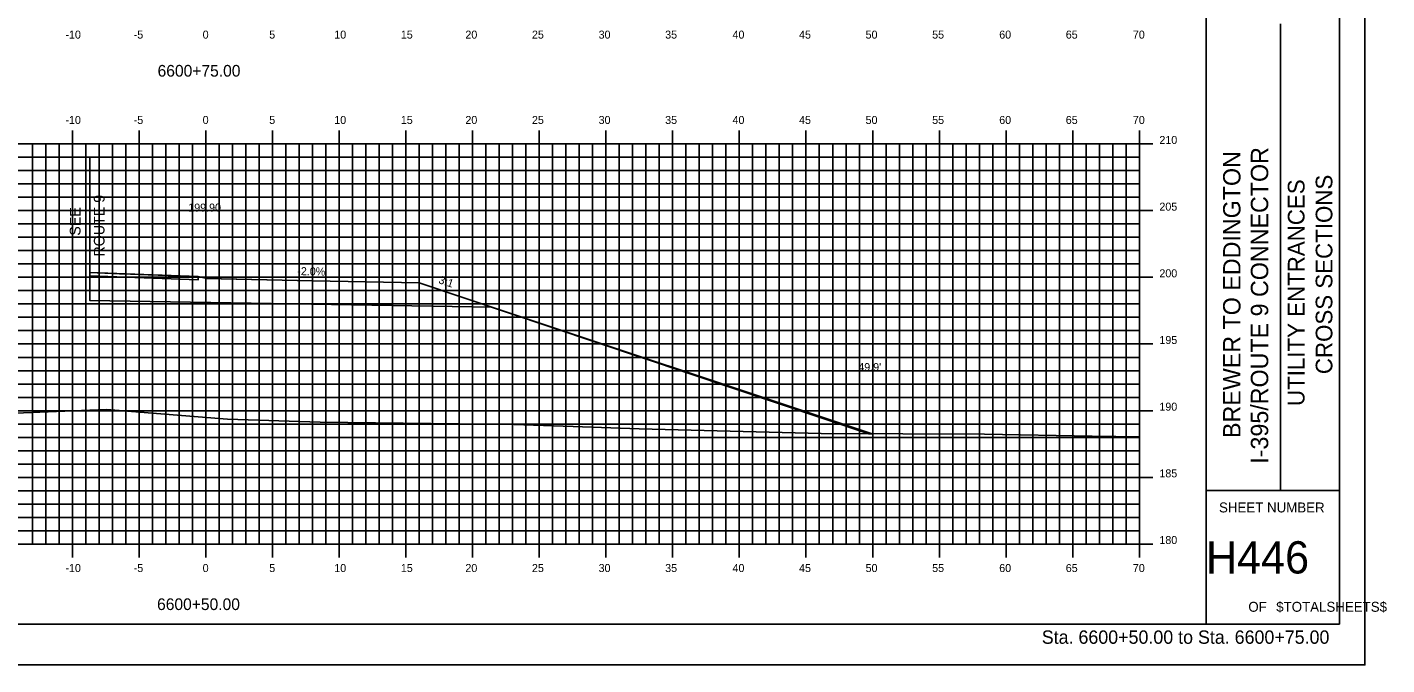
# Model space of a CAD drawing. Extents: x 1723296 to 1723468, y 459560 to 459670.
# Drawn here: x 1723365.8 to 1723467.8, y 459559.6 to 459607.4 of the extents above; entities that cross this region are included whole.
import ezdxf

# ---------------------------------------------------------------- set-up
doc = ezdxf.new("R2010")
doc.units = 0
for name, color, linetype in [('ANNOTATION', 7, 'Continuous'), ('BORDER', 7, 'Continuous'), ('D_Roadway_Centerline', 7, 'Continuous'), ('D_Roadway_Centerline_Text', 7, 'Continuous'), ('D_Roadway_Drive_Gravel', 7, 'Continuous'), ('D_Roadway_Edge_Shoulder', 7, 'Continuous'), ('D_Roadway_Edge_TW', 7, 'Continuous'), ('D_Roadway_Pavement', 7, 'Continuous'), ('D_Roadway_SlopeLines', 7, 'Continuous'), ('D_Roadway_SubGrade', 7, 'Continuous'), ('D_Text_Standard', 7, 'Continuous'), ('H_V ANNOTATION', 7, 'Continuous'), ('HIGHWAY_TITLE', 7, 'Continuous'), ('MAJOR', 7, 'Continuous'), ('MINOR', 7, 'Continuous'), ('PLOT BOUNDARY', 7, 'Continuous'), ('S_Roadway_Centerline', 7, 'Continuous')]:
    doc.layers.add(name, color=color, linetype=linetype)

msp = doc.modelspace()

# ---------------------------------------------------------------- linework, layer by layer
msp.add_lwpolyline([(1723379.2, 459588.51), (1723387.2, 459588.35), (1723395.2, 459588.19), (1723398.39, 459587.13), (1723428.91, 459576.88), (1723428.99, 459576.88), (1723429.03, 459576.88), (1723429.15, 459576.88)])
at = {"layer": 'BORDER'}
for p, q in [((1723454.2, 459562.61), (1723454.2, 459667.61)), ((1723459.79, 459572.62), (1723459.79, 459607.62)), ((1723454.2, 459572.62), (1723464.2, 459572.62))]:
    msp.add_line(p, q, dxfattribs=at)
msp.add_lwpolyline([(1723304.2, 459562.61), (1723464.2, 459562.61), (1723464.2, 459667.61), (1723304.2, 459667.61)], close=True, dxfattribs=at)
at = {"layer": 'D_Roadway_Centerline'}
msp.add_lwpolyline([(1723370.5, 459588.96), (1723372.73, 459588.88), (1723373.54, 459588.85), (1723374.88, 459588.8), (1723378.62, 459588.66), (1723379.24, 459588.51)], dxfattribs=at)
at = {"layer": 'D_Roadway_Drive_Gravel'}
msp.add_lwpolyline([(1723379.24, 459588.51), (1723387.2, 459588.35), (1723395.2, 459588.19), (1723398.39, 459587.13)], dxfattribs=at)
at = {"layer": 'D_Roadway_Edge_Shoulder'}
msp.add_lwpolyline([(1723370.5, 459588.96), (1723378.62, 459588.66), (1723378.62, 459588.41), (1723370.5, 459588.71)], close=True, dxfattribs=at)
msp.add_lwpolyline([(1723370.5, 459588.96), (1723378.62, 459588.66), (1723378.62, 459588.41), (1723370.5, 459588.71)], close=True, dxfattribs=at)
at = {"layer": 'D_Roadway_Edge_TW'}
msp.add_line((1723370.5, 459588.96), (1723370.5, 459588.71), dxfattribs=at)
msp.add_line((1723370.5, 459588.96), (1723370.5, 459588.71), dxfattribs=at)
msp.add_line((1723370.5, 459588.96), (1723370.5, 459588.71), dxfattribs=at)
at = {"layer": 'D_Roadway_Pavement'}
msp.add_line((1723370.5, 459588.71), (1723370.5, 459588.29), dxfattribs=at)
msp.add_line((1723370.5, 459588.71), (1723370.5, 459588.29), dxfattribs=at)
msp.add_lwpolyline([(1723370.5, 459588.71), (1723370.5, 459588.29)], dxfattribs=at)
at = {"layer": 'D_Roadway_SlopeLines'}
for points in [[(1723378.62, 459588.66), (1723379.24, 459588.51)], [(1723378.62, 459588.66), (1723379.24, 459588.51)], [(1723378.62, 459588.66), (1723379.24, 459588.51)], [(1723378.62, 459588.66), (1723379.24, 459588.51)], [(1723378.62, 459588.66), (1723379.24, 459588.51)], [(1723378.62, 459588.66), (1723379.24, 459588.51)], [(1723378.62, 459588.66), (1723379.24, 459588.51)], [(1723395.2, 459588.19), (1723398.39, 459587.13), (1723429.15, 459576.88)]]:
    msp.add_lwpolyline(points, dxfattribs=at)
at = {"layer": 'D_Roadway_SubGrade'}
for p, q in [((1723370.5, 459597.66), (1723370.5, 459586.87)), ((1723370.5, 459588.71), (1723370.5, 459586.87)), ((1723387.11, 459586.6), (1723400.66, 459586.37))]:
    msp.add_line(p, q, dxfattribs=at)
for points in [[(1723387.11, 459586.6), (1723370.5, 459586.87), (1723370.5, 459588.29), (1723370.5, 459588.71), (1723378.62, 459588.41), (1723378.62, 459588.66), (1723379.24, 459588.51)], [(1723387.11, 459586.6), (1723370.5, 459586.87), (1723370.5, 459588.71), (1723378.62, 459588.41), (1723378.62, 459588.66), (1723379.24, 459588.51)], [(1723370.5, 459588.71), (1723378.62, 459588.41), (1723378.62, 459588.66), (1723379.24, 459588.51)], [(1723370.5, 459588.71), (1723378.62, 459588.41), (1723378.62, 459588.66), (1723379.24, 459588.51)], [(1723370.5, 459588.29), (1723370.5, 459588.71), (1723370.5, 459586.87)], [(1723387.11, 459586.6), (1723370.5, 459586.87)], [(1723387.11, 459586.6), (1723370.5, 459586.87)]]:
    msp.add_lwpolyline(points, dxfattribs=at)
at = {"layer": 'MAJOR'}
for p, q in [((1723369.2, 459599.61), (1723369.2, 459598.61)), ((1723374.2, 459599.61), (1723374.2, 459598.61)), ((1723379.2, 459599.61), (1723379.2, 459598.61)), ((1723384.2, 459599.61), (1723384.2, 459598.61)), ((1723389.2, 459599.61), (1723389.2, 459598.61)), ((1723394.2, 459599.61), (1723394.2, 459598.61)), ((1723399.2, 459599.61), (1723399.2, 459598.61)), ((1723404.2, 459599.61), (1723404.2, 459598.61)), ((1723409.2, 459599.61), (1723409.2, 459598.61)), ((1723414.2, 459599.61), (1723414.2, 459598.61)), ((1723419.2, 459599.61), (1723419.2, 459598.61)), ((1723424.2, 459599.61), (1723424.2, 459598.61)), ((1723429.2, 459599.61), (1723429.2, 459598.61)), ((1723434.2, 459599.61), (1723434.2, 459598.61)), ((1723439.2, 459599.61), (1723439.2, 459598.61)), ((1723444.2, 459599.61), (1723444.2, 459598.61)), ((1723449.2, 459599.61), (1723449.2, 459598.61)), ((1723309.2, 459598.61), (1723449.2, 459598.61)), ((1723309.2, 459598.61), (1723449.2, 459598.61)), ((1723369.2, 459568.61), (1723369.2, 459598.61)), ((1723374.2, 459568.61), (1723374.2, 459598.61)), ((1723379.2, 459568.61), (1723379.2, 459598.61)), ((1723384.2, 459568.61), (1723384.2, 459598.61)), ((1723389.2, 459568.61), (1723389.2, 459598.61)), ((1723394.2, 459568.61), (1723394.2, 459598.61)), ((1723399.2, 459568.61), (1723399.2, 459598.61)), ((1723404.2, 459568.61), (1723404.2, 459598.61)), ((1723409.2, 459568.61), (1723409.2, 459598.61)), ((1723414.2, 459568.61), (1723414.2, 459598.61)), ((1723419.2, 459568.61), (1723419.2, 459598.61)), ((1723424.2, 459568.61), (1723424.2, 459598.61)), ((1723429.2, 459568.61), (1723429.2, 459598.61)), ((1723434.2, 459568.61), (1723434.2, 459598.61)), ((1723439.2, 459568.61), (1723439.2, 459598.61)), ((1723444.2, 459568.61), (1723444.2, 459598.61)), ((1723450.21, 459598.61), (1723448.2, 459598.61)), ((1723449.2, 459568.61), (1723449.2, 459598.61)), ((1723449.2, 459568.61), (1723449.2, 459598.61)), ((1723309.2, 459593.61), (1723449.2, 459593.61)), ((1723450.21, 459593.61), (1723448.2, 459593.61)), ((1723309.2, 459588.61), (1723449.2, 459588.61)), ((1723450.21, 459588.61), (1723448.2, 459588.61)), ((1723309.2, 459583.61), (1723449.2, 459583.61)), ((1723450.21, 459583.61), (1723448.2, 459583.61)), ((1723309.2, 459578.61), (1723449.2, 459578.61)), ((1723450.21, 459578.61), (1723448.2, 459578.61)), ((1723309.2, 459573.61), (1723449.2, 459573.61)), ((1723450.21, 459573.61), (1723448.2, 459573.61)), ((1723309.2, 459568.61), (1723449.2, 459568.61)), ((1723309.2, 459568.61), (1723449.2, 459568.61)), ((1723369.2, 459567.61), (1723369.2, 459568.61)), ((1723374.2, 459567.61), (1723374.2, 459568.61)), ((1723379.2, 459567.61), (1723379.2, 459568.61)), ((1723384.2, 459567.61), (1723384.2, 459568.61)), ((1723389.2, 459567.61), (1723389.2, 459568.61)), ((1723394.2, 459567.61), (1723394.2, 459568.61)), ((1723399.2, 459567.61), (1723399.2, 459568.61)), ((1723404.2, 459567.61), (1723404.2, 459568.61)), ((1723409.2, 459567.61), (1723409.2, 459568.61)), ((1723414.2, 459567.61), (1723414.2, 459568.61)), ((1723419.2, 459567.61), (1723419.2, 459568.61)), ((1723424.2, 459567.61), (1723424.2, 459568.61)), ((1723429.2, 459567.61), (1723429.2, 459568.61)), ((1723434.2, 459567.61), (1723434.2, 459568.61)), ((1723439.2, 459567.61), (1723439.2, 459568.61)), ((1723444.2, 459567.61), (1723444.2, 459568.61)), ((1723450.21, 459568.61), (1723448.2, 459568.61)), ((1723449.2, 459567.61), (1723449.2, 459568.61))]:
    msp.add_line(p, q, dxfattribs=at)
at = {"layer": 'MINOR'}
for p, q in [((1723366.2, 459568.61), (1723366.2, 459598.61)), ((1723367.2, 459568.61), (1723367.2, 459598.61)), ((1723368.2, 459568.61), (1723368.2, 459598.61)), ((1723370.2, 459568.61), (1723370.2, 459598.61)), ((1723371.2, 459568.61), (1723371.2, 459598.61)), ((1723372.2, 459568.61), (1723372.2, 459598.61)), ((1723373.2, 459568.61), (1723373.2, 459598.61)), ((1723375.2, 459568.61), (1723375.2, 459598.61)), ((1723376.2, 459568.61), (1723376.2, 459598.61)), ((1723377.2, 459568.61), (1723377.2, 459598.61)), ((1723378.2, 459568.61), (1723378.2, 459598.61)), ((1723380.2, 459568.61), (1723380.2, 459598.61)), ((1723381.2, 459568.61), (1723381.2, 459598.61)), ((1723382.2, 459568.61), (1723382.2, 459598.61)), ((1723383.2, 459568.61), (1723383.2, 459598.61)), ((1723385.2, 459568.61), (1723385.2, 459598.61)), ((1723386.2, 459568.61), (1723386.2, 459598.61)), ((1723387.2, 459568.61), (1723387.2, 459598.61)), ((1723388.2, 459568.61), (1723388.2, 459598.61)), ((1723390.2, 459568.61), (1723390.2, 459598.61)), ((1723391.2, 459568.61), (1723391.2, 459598.61)), ((1723392.2, 459568.61), (1723392.2, 459598.61)), ((1723393.2, 459568.61), (1723393.2, 459598.61)), ((1723395.2, 459568.61), (1723395.2, 459598.61)), ((1723396.2, 459568.61), (1723396.2, 459598.61)), ((1723397.2, 459568.61), (1723397.2, 459598.61)), ((1723398.2, 459568.61), (1723398.2, 459598.61)), ((1723400.2, 459568.61), (1723400.2, 459598.61)), ((1723401.2, 459568.61), (1723401.2, 459598.61)), ((1723402.2, 459568.61), (1723402.2, 459598.61)), ((1723403.2, 459568.61), (1723403.2, 459598.61)), ((1723405.2, 459568.61), (1723405.2, 459598.61)), ((1723406.2, 459568.61), (1723406.2, 459598.61)), ((1723407.2, 459568.61), (1723407.2, 459598.61)), ((1723408.2, 459568.61), (1723408.2, 459598.61)), ((1723410.2, 459568.61), (1723410.2, 459598.61)), ((1723411.2, 459568.61), (1723411.2, 459598.61)), ((1723412.2, 459568.61), (1723412.2, 459598.61)), ((1723413.2, 459568.61), (1723413.2, 459598.61)), ((1723415.2, 459568.61), (1723415.2, 459598.61)), ((1723416.2, 459568.61), (1723416.2, 459598.61)), ((1723417.2, 459568.61), (1723417.2, 459598.61)), ((1723418.2, 459568.61), (1723418.2, 459598.61)), ((1723420.2, 459568.61), (1723420.2, 459598.61)), ((1723421.2, 459568.61), (1723421.2, 459598.61)), ((1723422.2, 459568.61), (1723422.2, 459598.61)), ((1723423.2, 459568.61), (1723423.2, 459598.61)), ((1723425.2, 459568.61), (1723425.2, 459598.61)), ((1723426.2, 459568.61), (1723426.2, 459598.61)), ((1723427.2, 459568.61), (1723427.2, 459598.61)), ((1723428.2, 459568.61), (1723428.2, 459598.61)), ((1723430.2, 459568.61), (1723430.2, 459598.61)), ((1723431.2, 459568.61), (1723431.2, 459598.61)), ((1723432.2, 459568.61), (1723432.2, 459598.61)), ((1723433.2, 459568.61), (1723433.2, 459598.61)), ((1723435.2, 459568.61), (1723435.2, 459598.61)), ((1723436.2, 459568.61), (1723436.2, 459598.61)), ((1723437.2, 459568.61), (1723437.2, 459598.61)), ((1723438.2, 459568.61), (1723438.2, 459598.61)), ((1723440.2, 459568.61), (1723440.2, 459598.61)), ((1723441.2, 459568.61), (1723441.2, 459598.61)), ((1723442.2, 459568.61), (1723442.2, 459598.61)), ((1723443.2, 459568.61), (1723443.2, 459598.61)), ((1723445.2, 459568.61), (1723445.2, 459598.61)), ((1723446.2, 459568.61), (1723446.2, 459598.61)), ((1723447.2, 459568.61), (1723447.2, 459598.61)), ((1723448.2, 459568.61), (1723448.2, 459598.61)), ((1723309.2, 459597.61), (1723449.2, 459597.61)), ((1723449.2, 459597.61), (1723448.2, 459597.61)), ((1723309.2, 459596.61), (1723449.2, 459596.61)), ((1723449.2, 459596.61), (1723448.2, 459596.61)), ((1723309.2, 459595.61), (1723449.2, 459595.61)), ((1723449.2, 459595.61), (1723448.2, 459595.61)), ((1723309.2, 459594.61), (1723449.2, 459594.61)), ((1723449.2, 459594.61), (1723448.2, 459594.61)), ((1723309.2, 459592.61), (1723449.2, 459592.61)), ((1723449.2, 459592.61), (1723448.2, 459592.61)), ((1723309.2, 459591.61), (1723449.2, 459591.61)), ((1723449.2, 459591.61), (1723448.2, 459591.61)), ((1723309.2, 459590.61), (1723449.2, 459590.61)), ((1723449.2, 459590.61), (1723448.2, 459590.61)), ((1723309.2, 459589.61), (1723449.2, 459589.61)), ((1723449.2, 459589.61), (1723448.2, 459589.61)), ((1723309.2, 459587.61), (1723449.2, 459587.61)), ((1723449.2, 459587.61), (1723448.2, 459587.61)), ((1723309.2, 459586.61), (1723449.2, 459586.61)), ((1723449.2, 459586.61), (1723448.2, 459586.61)), ((1723309.2, 459585.61), (1723449.2, 459585.61)), ((1723449.2, 459585.61), (1723448.2, 459585.61)), ((1723309.2, 459584.61), (1723449.2, 459584.61)), ((1723449.2, 459584.61), (1723448.2, 459584.61)), ((1723309.2, 459582.61), (1723449.2, 459582.61)), ((1723449.2, 459582.61), (1723448.2, 459582.61)), ((1723309.2, 459581.61), (1723449.2, 459581.61)), ((1723449.2, 459581.61), (1723448.2, 459581.61)), ((1723309.2, 459580.61), (1723449.2, 459580.61)), ((1723449.2, 459580.61), (1723448.2, 459580.61)), ((1723309.2, 459579.61), (1723449.2, 459579.61)), ((1723449.2, 459579.61), (1723448.2, 459579.61)), ((1723309.2, 459577.61), (1723449.2, 459577.61)), ((1723449.2, 459577.61), (1723448.2, 459577.61)), ((1723309.2, 459576.61), (1723449.2, 459576.61)), ((1723449.2, 459576.61), (1723448.2, 459576.61)), ((1723309.2, 459575.61), (1723449.2, 459575.61)), ((1723449.2, 459575.61), (1723448.2, 459575.61)), ((1723309.2, 459574.61), (1723449.2, 459574.61)), ((1723449.2, 459574.61), (1723448.2, 459574.61)), ((1723309.2, 459572.61), (1723449.2, 459572.61)), ((1723449.2, 459572.61), (1723448.2, 459572.61)), ((1723309.2, 459571.61), (1723449.2, 459571.61)), ((1723449.2, 459571.61), (1723448.2, 459571.61)), ((1723309.2, 459570.61), (1723449.2, 459570.61)), ((1723449.2, 459570.61), (1723448.2, 459570.61)), ((1723309.2, 459569.61), (1723449.2, 459569.61)), ((1723449.2, 459569.61), (1723448.2, 459569.61))]:
    msp.add_line(p, q, dxfattribs=at)
at = {"layer": 'PLOT BOUNDARY'}
msp.add_lwpolyline([(1723296.11, 459559.55), (1723466.11, 459559.55), (1723466.11, 459669.55), (1723296.11, 459669.55)], close=True, dxfattribs=at)
at = {"layer": 'S_Roadway_Centerline'}
msp.add_lwpolyline([(1723309.2, 459579.55), (1723311.22, 459579.51), (1723316.24, 459579.55), (1723335.26, 459578.97), (1723338.56, 459578.89), (1723348.8, 459579), (1723359.81, 459578.24), (1723360.1, 459578.23), (1723360.49, 459578.24), (1723371.74, 459578.69), (1723380.82, 459577.97), (1723387.77, 459577.74), (1723402.29, 459577.58), (1723406.73, 459577.43), (1723411.68, 459577.24), (1723425.33, 459576.89), (1723437.59, 459576.84), (1723445.67, 459576.71), (1723449.2, 459576.66)], dxfattribs=at)

# ---------------------------------------------------------------- texts
at = {"layer": 'ANNOTATION'}
for s, height, rotation, p in [('ROUTE 9', 0.8, 90, (1723371.6, 459590.16)), ('SEE', 0.8, 90, (1723369.8, 459591.73)), ('-2.0%', 0.6, 358.8542, (1723386.05, 459588.78)), ('3:1', 0.6, 341.5651, (1723396.6, 459588.18))]:
    msp.add_text(s, height=height, rotation=rotation, dxfattribs=at).set_placement(p)
at = {"layer": 'BORDER'}
for s, p in [('UTILITY ENTRANCES', (1723461.58, 459578.96)), ('CROSS SECTIONS', (1723463.67, 459581.35))]:
    msp.add_text(s, height=1.25, rotation=90, dxfattribs=at).set_placement(p)
for s, height, p in [('SHEET NUMBER', 0.7453, (1723455.17, 459570.98)), ('H446', 2.419, (1723454.19, 459566.4)), ('OF', 0.745, (1723457.37, 459563.53)), ('$TOTALSHEETS$', 0.7453, (1723459.46, 459563.53))]:
    msp.add_text(s, height=height, dxfattribs=at).set_placement(p)
at = {"layer": 'D_Roadway_Centerline_Text'}
msp.add_text('199.90', height=0.6, dxfattribs=at).set_placement((1723377.88, 459593.54))
at = {"layer": 'D_Text_Standard'}
msp.add_text("49.9'", height=0.6, dxfattribs=at).set_placement((1723428.12, 459581.58))
at = {"layer": 'H_V ANNOTATION'}
for s, height, p in [('-10', 0.6, (1723368.67, 459606.51)), ('-5', 0.6, (1723373.79, 459606.51)), ('0', 0.6, (1723378.96, 459606.51)), ('5', 0.6, (1723383.95, 459606.51)), ('10', 0.6, (1723388.83, 459606.51)), ('15', 0.6, (1723393.82, 459606.51)), ('20', 0.6, (1723398.66, 459606.51)), ('25', 0.6, (1723403.65, 459606.51)), ('30', 0.6, (1723408.65, 459606.51)), ('35', 0.6, (1723413.64, 459606.51)), ('40', 0.6, (1723418.69, 459606.51)), ('45', 0.6, (1723423.68, 459606.51)), ('50', 0.6, (1723428.67, 459606.51)), ('55', 0.6, (1723433.66, 459606.51)), ('60', 0.6, (1723438.69, 459606.51)), ('65', 0.6, (1723443.68, 459606.51)), ('70', 0.6, (1723448.71, 459606.51)), ('6600+75.00', 0.875, (1723375.58, 459603.66)), ('-10', 0.6, (1723368.67, 459600.11)), ('-5', 0.6, (1723373.79, 459600.11)), ('0', 0.6, (1723378.96, 459600.11)), ('5', 0.6, (1723383.95, 459600.11)), ('10', 0.6, (1723388.83, 459600.11)), ('15', 0.6, (1723393.82, 459600.11)), ('20', 0.6, (1723398.66, 459600.11)), ('25', 0.6, (1723403.65, 459600.11)), ('30', 0.6, (1723408.65, 459600.11)), ('35', 0.6, (1723413.64, 459600.11)), ('40', 0.6, (1723418.69, 459600.11)), ('45', 0.6, (1723423.68, 459600.11)), ('50', 0.6, (1723428.67, 459600.11)), ('55', 0.6, (1723433.66, 459600.11)), ('60', 0.6, (1723438.69, 459600.11)), ('65', 0.6, (1723443.68, 459600.11)), ('70', 0.6, (1723448.71, 459600.11)), ('210', 0.6, (1723450.7, 459598.61)), ('205', 0.6, (1723450.7, 459593.61)), ('200', 0.6, (1723450.7, 459588.61)), ('195', 0.6, (1723450.7, 459583.61)), ('190', 0.6, (1723450.7, 459578.61)), ('185', 0.6, (1723450.7, 459573.61)), ('180', 0.6, (1723450.7, 459568.61)), ('-10', 0.6, (1723368.67, 459566.51)), ('-5', 0.6, (1723373.79, 459566.51)), ('0', 0.6, (1723378.96, 459566.51)), ('5', 0.6, (1723383.95, 459566.51)), ('10', 0.6, (1723388.83, 459566.51)), ('15', 0.6, (1723393.82, 459566.51)), ('20', 0.6, (1723398.66, 459566.51)), ('25', 0.6, (1723403.65, 459566.51)), ('30', 0.6, (1723408.65, 459566.51)), ('35', 0.6, (1723413.64, 459566.51)), ('40', 0.6, (1723418.69, 459566.51)), ('45', 0.6, (1723423.68, 459566.51)), ('50', 0.6, (1723428.67, 459566.51)), ('55', 0.6, (1723433.66, 459566.51)), ('60', 0.6, (1723438.69, 459566.51)), ('65', 0.6, (1723443.68, 459566.51)), ('70', 0.6, (1723448.71, 459566.51)), ('6600+50.00', 0.875, (1723375.54, 459563.66)), ('Sta. 6600+50.00 to Sta. 6600+75.00', 1.0002, (1723441.88, 459561.13))]:
    msp.add_text(s, height=height, dxfattribs=at).set_placement(p)
at = {"layer": 'HIGHWAY_TITLE'}
for s, p in [('BREWER TO EDDINGTON', (1723456.78, 459576.56)), ('I-395/ROUTE 9 CONNECTOR', (1723458.86, 459574.63))]:
    msp.add_text(s, height=1.3043, rotation=90, dxfattribs=at).set_placement(p)

doc.saveas('drawing.dxf')
